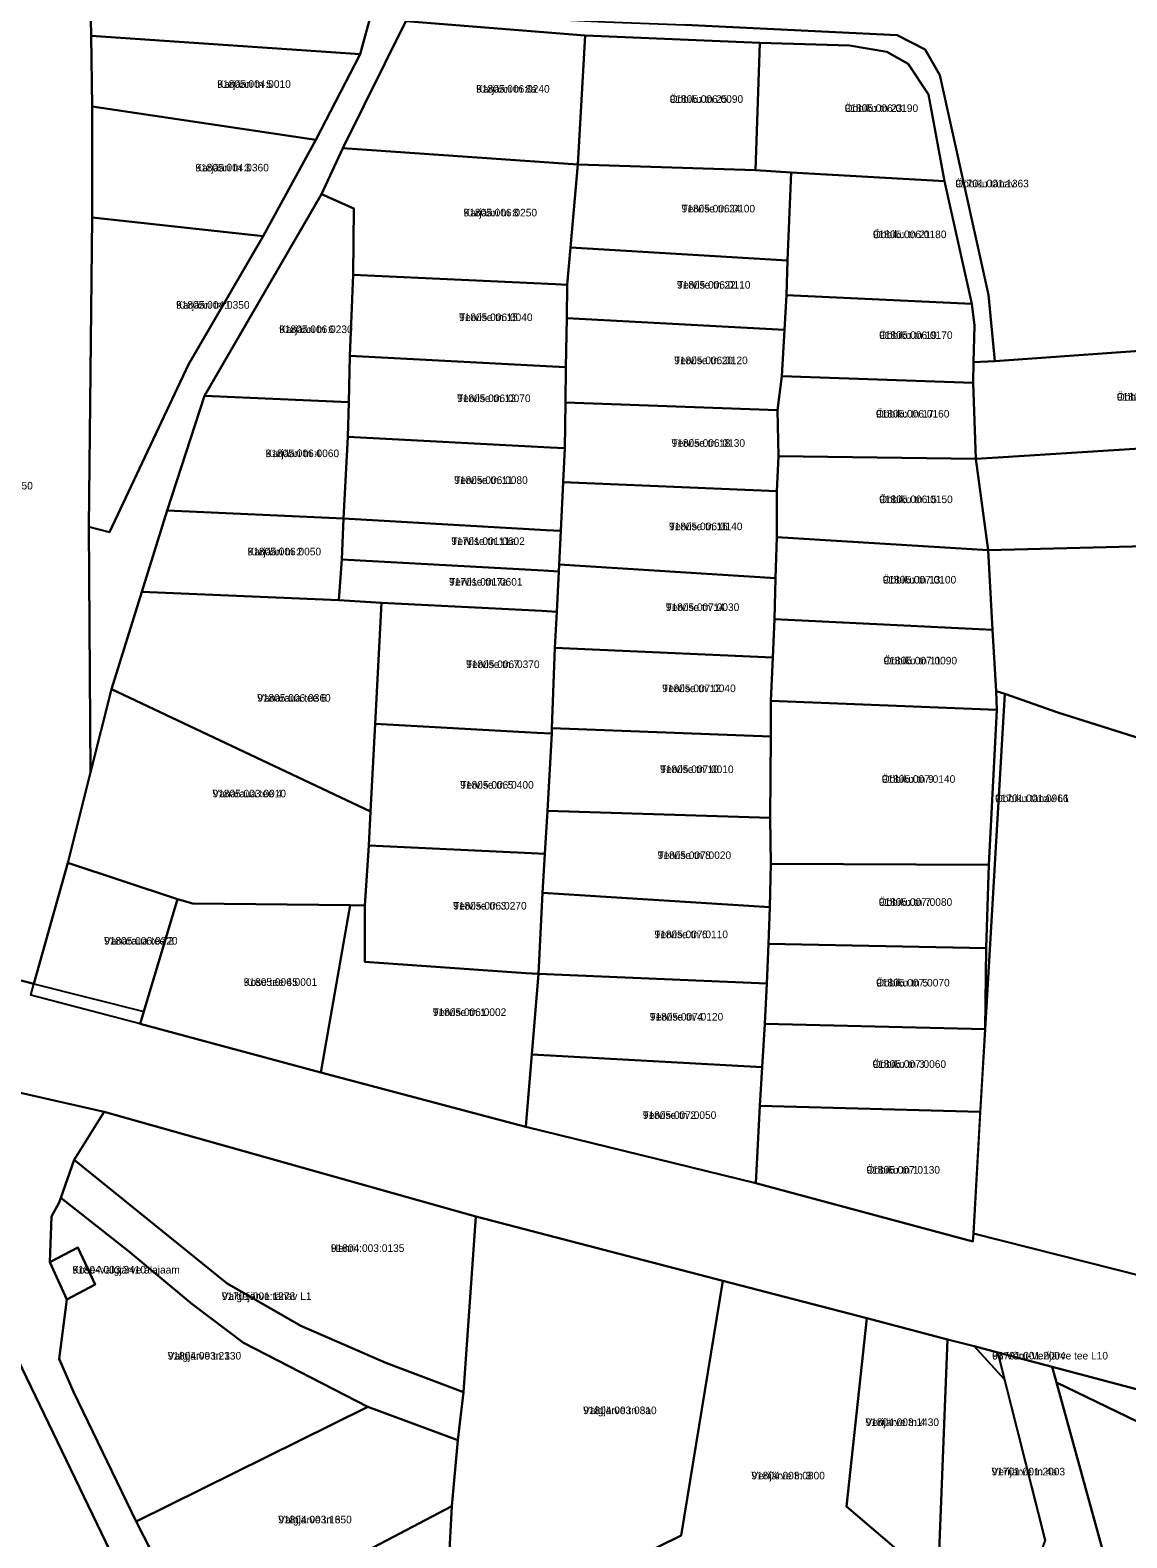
# Model space of a CAD drawing. Extents: x 655954 to 711923, y 6395079 to 6429745.
# Drawn here: x 680691.2 to 680907.6, y 6411990.7 to 6412288.3 of the extents above; entities that cross this region are included whole.
import ezdxf

# ---------------------------------------------------------------- set-up
doc = ezdxf.new("R2010")
doc.units = 0
for name, color, linetype in [('L_AADRESS', 7, 'Continuous'), ('PIIR', 7, 'Continuous'), ('TUNNUS', 7, 'Continuous')]:
    doc.layers.add(name, color=color, linetype=linetype)

msp = doc.modelspace()

# ---------------------------------------------------------------- linework, layer by layer
at = {"layer": 'PIIR'}
for points in [[(680680.44, 6412556.2), (680693.94, 6412462.74), (680699, 6412413.21), (680701.22, 6412382.72), (680702.09, 6412366.63), (680702.52, 6412349.92), (680702.33, 6412333.42), (680702.73, 6412319.59), (680702.93, 6412303.72), (680703.22, 6412287.2), (680703.43, 6412273.22), (680703.41, 6412251.32), (680702.8, 6412190.26), (680703.14, 6412141.77), (680698.64, 6412123.91), (680691.94, 6412100.04), (680672.88, 6412104.96)], [(680765.34, 6412290.1), (680752.9, 6412265.02), (680748.69, 6412255.94), (680725.61, 6412216.14), (680718.25, 6412193.46), (680713.24, 6412177.42), (680707.28, 6412158.21), (680703.14, 6412141.77), (680702.8, 6412190.26), (680706.83, 6412189.19), (680722.42, 6412222.3), (680737.18, 6412247.62), (680747.58, 6412266.64), (680756.31, 6412283.58), (680760.94, 6412300.49)], [(680933.18, 6412226.66), (680881.55, 6412222.94), (680880.28, 6412236.06), (680870.69, 6412279.41), (680867.78, 6412284.5), (680862.31, 6412287.31), (680820.36, 6412289.35)], [(680938.72, 6412035.25), (680877.31, 6412050.78), (680878.8, 6412076.38), (680879.65, 6412091.1), (680883.54, 6412157.28), (680894.01, 6412153.62), (680910.4, 6412148.38)], [(680672.88, 6412104.96), (680691.94, 6412100.04), (680713.61, 6412094.57), (680712.89, 6412092.18), (680748.53, 6412082.52), (680786.53, 6412072.49), (680788.99, 6412071.84), (680834.37, 6412060.69), (680877.19, 6412049.18), (680877.31, 6412050.78), (680938.72, 6412035.25), (680958.41, 6412030.09), (680992.85, 6412021.05), (680998.02, 6412019.7), (681048.15, 6412005.85), (681072.23, 6411999.62), (681095.85, 6411993.91), (681114.62, 6411989.2), (681131.81, 6411985.29), (681142.64, 6411981.4), (681196.38, 6411968), (681251.89, 6411953.79)], [(681715.24, 6411810.02), (681453.34, 6411877.71), (681294.84, 6411919.24), (681247.61, 6411931.95), (681196.28, 6411945.45), (681144.95, 6411958.58), (681138, 6411960.36), (681067.39, 6411978.82), (681030.99, 6411988.27), (680959.83, 6412006.81), (680933.06, 6412013.75), (680892.85, 6412024.44), (680882.14, 6412027.25), (680877.44, 6412028.49), (680872.22, 6412029.86), (680856.28, 6412034.04), (680827.85, 6412041.39), (680779.17, 6412054.12), (680705.81, 6412074.78), (680677.03, 6412081.28)], [(680677.03, 6412081.28), (680705.81, 6412074.78), (680699.91, 6412065.3), (680697.25, 6412057.81), (680696.92, 6412056.89), (680695.4, 6412054.12), (680695.07, 6412045.07), (680698.46, 6412037.72), (680696.92, 6412026.03), (680699.73, 6412019.48), (680712.13, 6411993.93), (680724.06, 6411970.51)], [(680713.98, 6411973.54), (680684.39, 6412034.88)], [(680891.46, 6411990.2), (680882.14, 6412027.25), (680892.85, 6412024.44), (680893.69, 6412021.37), (680905.86, 6411977.12)], [(680905.86, 6411977.12), (680893.69, 6412021.37), (680921.45, 6412007.92), (680932.14, 6412005.16), (680933.52, 6411996.33), (680936.54, 6411993.46), (680947.76, 6411994.27), (680949.96, 6411993.29), (680959.44, 6411986.97)]]:
    msp.add_lwpolyline(points, dxfattribs=at)
for points in [[(680760.94, 6412300.49), (680756.31, 6412283.58), (680703.22, 6412287.2), (680702.93, 6412303.72)], [(680752.9, 6412265.02), (680765.34, 6412290.1), (680800.73, 6412287.27), (680799.29, 6412261.81)], [(680870.69, 6412279.41), (680880.28, 6412236.06), (680881.55, 6412222.94), (680877.37, 6412222.76), (680877.54, 6412230), (680877.04, 6412234.3), (680871.65, 6412258.51), (680868.45, 6412275.6), (680864.46, 6412281.65), (680860.25, 6412284.01), (680852.84, 6412285.3), (680835.2, 6412285.8), (680800.73, 6412287.27), (680765.34, 6412290.1), (680767.12, 6412291.79), (680804.61, 6412289.94), (680820.36, 6412289.35), (680862.31, 6412287.31), (680867.78, 6412284.5)], [(680756.31, 6412283.58), (680747.58, 6412266.64), (680703.43, 6412273.22), (680703.22, 6412287.2)], [(680835.2, 6412285.8), (680834.35, 6412260.66), (680799.29, 6412261.81), (680800.73, 6412287.27)], [(680835.2, 6412285.8), (680852.84, 6412285.3), (680860.25, 6412284.01), (680864.46, 6412281.65), (680868.45, 6412275.6), (680871.65, 6412258.51), (680841.34, 6412260.19), (680834.35, 6412260.66)], [(680747.58, 6412266.64), (680737.18, 6412247.62), (680703.41, 6412251.32), (680703.43, 6412273.22)], [(680799.29, 6412261.81), (680797.82, 6412245.4), (680797.18, 6412238.06), (680794.89, 6412238.16), (680754.94, 6412239.99), (680755.08, 6412253.09), (680748.69, 6412255.94), (680752.9, 6412265.02)], [(680799.29, 6412261.81), (680834.35, 6412260.66), (680841.34, 6412260.19), (680840.67, 6412242.85), (680797.82, 6412245.4)], [(680840.46, 6412236.01), (680840.67, 6412242.85), (680841.34, 6412260.19), (680871.65, 6412258.51), (680877.04, 6412234.3)], [(680748.69, 6412255.94), (680755.08, 6412253.09), (680754.94, 6412239.99), (680754.31, 6412224.01), (680754.06, 6412214.85), (680725.61, 6412216.14)], [(680722.42, 6412222.3), (680706.83, 6412189.19), (680702.8, 6412190.26), (680703.41, 6412251.32), (680737.18, 6412247.62)], [(680797.08, 6412231.45), (680797.18, 6412238.06), (680797.82, 6412245.4), (680840.67, 6412242.85), (680840.46, 6412236.01), (680840.05, 6412229.16)], [(680754.31, 6412224.01), (680754.94, 6412239.99), (680794.89, 6412238.16), (680797.18, 6412238.06), (680797.08, 6412231.45), (680796.9, 6412221.77), (680794.26, 6412221.91)], [(680840.46, 6412236.01), (680877.04, 6412234.3), (680877.54, 6412230), (680877.37, 6412222.76), (680877.27, 6412218.69), (680839.53, 6412220), (680840.05, 6412229.16)], [(680840.05, 6412229.16), (680839.53, 6412220), (680838.65, 6412213.28), (680796.81, 6412214.83), (680796.9, 6412221.77), (680797.08, 6412231.45)], [(680882.15, 6412203.95), (680877.77, 6412203.66), (680877.27, 6412218.69), (680877.37, 6412222.76), (680881.55, 6412222.94), (680933.18, 6412226.66), (680934.3, 6412207.68), (680932.05, 6412207.12)], [(680753.87, 6412208.02), (680754.06, 6412214.85), (680754.31, 6412224.01), (680794.26, 6412221.91), (680796.9, 6412221.77), (680796.81, 6412214.83), (680796.69, 6412205.76), (680793.81, 6412205.92)], [(680877.27, 6412218.69), (680877.77, 6412203.66), (680838.87, 6412204.23), (680838.65, 6412213.28), (680839.53, 6412220)], [(680725.61, 6412216.14), (680754.06, 6412214.85), (680753.87, 6412208.02), (680753.03, 6412191.89), (680718.25, 6412193.46)], [(680838.65, 6412213.28), (680838.87, 6412204.23), (680838.51, 6412197.29), (680796.38, 6412199.08), (680796.69, 6412205.76), (680796.81, 6412214.83)], [(680753.03, 6412191.89), (680753.87, 6412208.02), (680793.81, 6412205.92), (680796.69, 6412205.76), (680796.38, 6412199.08), (680795.94, 6412189.44), (680793, 6412189.6)], [(680942.34, 6412187.24), (680880.22, 6412185.64), (680877.77, 6412203.66), (680882.15, 6412203.95), (680932.05, 6412207.12), (680934.3, 6412207.68), (680936.09, 6412202.44), (680940.09, 6412193.73)], [(680880.22, 6412185.64), (680838.56, 6412188.25), (680838.51, 6412197.29), (680838.87, 6412204.23), (680877.77, 6412203.66)], [(680838.51, 6412197.29), (680838.56, 6412188.25), (680838.3, 6412180.12), (680795.58, 6412182.85), (680795.94, 6412189.44), (680796.38, 6412199.08)], [(680718.25, 6412193.46), (680753.03, 6412191.89), (680752.7, 6412183.83), (680752.14, 6412175.81), (680713.24, 6412177.42)], [(680752.7, 6412183.83), (680753.03, 6412191.89), (680793, 6412189.6), (680795.94, 6412189.44), (680795.58, 6412182.85), (680795.52, 6412181.46), (680792.5, 6412181.65)], [(680880.22, 6412185.64), (680881.12, 6412169.9), (680838.1, 6412172.05), (680838.3, 6412180.12), (680838.56, 6412188.25)], [(680910.4, 6412148.38), (680894.01, 6412153.62), (680883.54, 6412157.28), (680881.81, 6412157.84), (680881.12, 6412169.9), (680880.22, 6412185.64), (680942.34, 6412187.24), (680942.89, 6412185.65), (680943.13, 6412183.74), (680943.17, 6412182.04), (680942.89, 6412180.73), (680941.35, 6412177.83), (680938.65, 6412173.58), (680934.19, 6412166.77), (680930.54, 6412161.41), (680927.17, 6412155.65), (680926.93, 6412154.82), (680926.32, 6412152.73), (680926.58, 6412150.84), (680912.52, 6412151.51), (680910.54, 6412151.62)], [(680752.14, 6412175.81), (680752.7, 6412183.83), (680792.5, 6412181.65), (680795.52, 6412181.46), (680795.12, 6412173.48), (680792.14, 6412173.66), (680760.52, 6412175.29)], [(680837.75, 6412164.44), (680794.76, 6412166.38), (680795.12, 6412173.48), (680795.52, 6412181.46), (680795.58, 6412182.85), (680838.3, 6412180.12), (680838.1, 6412172.05)], [(680707.28, 6412158.21), (680713.24, 6412177.42), (680752.14, 6412175.81), (680760.52, 6412175.29), (680759.27, 6412151.4), (680758.38, 6412134.06)], [(680759.27, 6412151.4), (680760.52, 6412175.29), (680792.14, 6412173.66), (680795.12, 6412173.48), (680794.76, 6412166.38), (680794.13, 6412150.49), (680794.14, 6412149.46), (680791.18, 6412149.62)], [(680881.93, 6412154.14), (680837.35, 6412155.92), (680837.75, 6412164.44), (680838.1, 6412172.05), (680881.12, 6412169.9), (680881.81, 6412157.84)], [(680794.76, 6412166.38), (680837.75, 6412164.44), (680837.35, 6412155.92), (680837.35, 6412148.88), (680794.13, 6412150.49)], [(680707.28, 6412158.21), (680758.38, 6412134.06), (680758, 6412127.38), (680757.22, 6412115.51), (680754.35, 6412115.56), (680723.27, 6412115.9), (680720.27, 6412116.78), (680698.64, 6412123.91), (680703.14, 6412141.77)], [(680837.35, 6412123.76), (680837.24, 6412132.84), (680837.35, 6412148.88), (680837.35, 6412155.92), (680881.93, 6412154.14), (680880.35, 6412123.54)], [(680880.35, 6412123.54), (680881.93, 6412154.14), (680881.81, 6412157.84), (680883.54, 6412157.28), (680879.65, 6412091.1), (680879.87, 6412107.11)], [(680758.38, 6412134.06), (680759.27, 6412151.4), (680791.18, 6412149.62), (680794.14, 6412149.46), (680793.26, 6412134.19), (680792.77, 6412125.74), (680790.11, 6412125.87), (680758, 6412127.38)], [(680794.13, 6412150.49), (680837.35, 6412148.88), (680837.24, 6412132.84), (680793.26, 6412134.19), (680794.14, 6412149.46)], [(680793.26, 6412134.19), (680837.24, 6412132.84), (680837.35, 6412123.76), (680837.16, 6412115.16), (680792.29, 6412118.01), (680792.77, 6412125.74)], [(680757.22, 6412115.51), (680758, 6412127.38), (680790.11, 6412125.87), (680792.77, 6412125.74), (680792.29, 6412118.01), (680791.48, 6412102.01), (680788.99, 6412102.18), (680757.22, 6412104.38)], [(680720.27, 6412116.78), (680713.61, 6412094.57), (680712.89, 6412092.18), (680691.31, 6412097.78), (680691.94, 6412100.04), (680698.64, 6412123.91)], [(680836.91, 6412107.93), (680837.16, 6412115.16), (680837.35, 6412123.76), (680880.35, 6412123.54), (680879.87, 6412107.11)], [(680713.61, 6412094.57), (680720.27, 6412116.78), (680723.27, 6412115.9), (680754.35, 6412115.56), (680748.53, 6412082.52), (680712.89, 6412092.18)], [(680792.29, 6412118.01), (680837.16, 6412115.16), (680836.91, 6412107.93), (680836.55, 6412100.1), (680791.48, 6412102.01)], [(680754.35, 6412115.56), (680757.22, 6412115.51), (680757.22, 6412104.38), (680788.99, 6412102.18), (680791.48, 6412102.01), (680790.17, 6412086.07), (680789.2, 6412074.33), (680788.99, 6412071.84), (680786.53, 6412072.49), (680748.53, 6412082.52)], [(680836.17, 6412092.15), (680836.55, 6412100.1), (680836.91, 6412107.93), (680879.87, 6412107.11), (680879.65, 6412091.1)], [(680791.48, 6412102.01), (680836.55, 6412100.1), (680836.17, 6412092.15), (680835.67, 6412083.58), (680790.17, 6412086.07)], [(680835.21, 6412075.96), (680835.67, 6412083.58), (680836.17, 6412092.15), (680879.65, 6412091.1), (680878.68, 6412074.78)], [(680788.99, 6412071.84), (680789.2, 6412074.33), (680790.17, 6412086.07), (680835.67, 6412083.58), (680835.21, 6412075.96), (680834.37, 6412060.69)], [(680834.37, 6412060.69), (680835.21, 6412075.96), (680878.68, 6412074.78), (680877.31, 6412050.78), (680877.19, 6412049.18)], [(680705.81, 6412074.78), (680779.17, 6412054.12), (680776.74, 6412019.45), (680761.41, 6412025.2), (680744.61, 6412032.55), (680730.06, 6412040.92), (680699.91, 6412065.3)], [(680776.74, 6412019.45), (680775.57, 6412009.98), (680757.85, 6412016.57), (680733.3, 6412029.15), (680723.13, 6412036.9), (680710.53, 6412047.33), (680697.25, 6412057.81), (680699.91, 6412065.3), (680730.06, 6412040.92), (680744.61, 6412032.55), (680761.41, 6412025.2)], [(680712.13, 6411993.93), (680699.73, 6412019.48), (680696.92, 6412026.03), (680698.46, 6412037.72), (680704, 6412040.68), (680700.63, 6412048), (680695.07, 6412045.07), (680695.4, 6412054.12), (680696.92, 6412056.89), (680697.25, 6412057.81), (680710.53, 6412047.33), (680723.13, 6412036.9), (680733.3, 6412029.15), (680757.85, 6412016.57), (680750.78, 6412013.05)], [(680779.17, 6412054.12), (680827.85, 6412041.39), (680819.65, 6411991.16), (680798.16, 6411980.54), (680772.8, 6411967.11), (680772.87, 6411968.3), (680774.4, 6411996.9), (680775.57, 6412009.98), (680776.74, 6412019.45)], [(680695.07, 6412045.07), (680700.63, 6412048), (680704, 6412040.68), (680698.46, 6412037.72)], [(680827.85, 6412041.39), (680856.28, 6412034.04), (680852.3, 6411996.87), (680868.87, 6411982.71), (680812.55, 6411953.72), (680798.16, 6411980.54), (680819.65, 6411991.16)], [(680676.96, 6412036.82), (680684.39, 6412034.88), (680713.98, 6411973.54), (680635.38, 6411927.25), (680633.49, 6411926.26), (680628.89, 6411931.55), (680620.27, 6411940.29), (680614.08, 6411945.87), (680608.86, 6411949.03), (680604.98, 6411952.79), (680600.49, 6411956.92), (680594.02, 6411961.84), (680595.49, 6411963.69), (680604.05, 6411974.9), (680611.8, 6412018.81), (680620.2, 6412023.18), (680625.29, 6412012.56)], [(680866.23, 6411976.51), (680868.87, 6411982.71), (680852.3, 6411996.87), (680856.28, 6412034.04), (680872.22, 6412029.86), (680870.35, 6411982.89), (680870.07, 6411975.87), (680895.55, 6411967.56), (680891.03, 6411954.2), (680882.6, 6411950.1), (680829.67, 6411924.45), (680816.54, 6411950.53)], [(680889.38, 6411984.65), (680885.22, 6411980.63), (680870.35, 6411982.89), (680872.22, 6412029.86), (680877.44, 6412028.49), (680883.48, 6412021.94), (680891.46, 6411990.2)], [(680882.14, 6412027.25), (680883.48, 6412021.94), (680877.44, 6412028.49)], [(680892.85, 6412024.44), (680933.06, 6412013.75), (680931.64, 6412008.37), (680932.14, 6412005.16), (680921.45, 6412007.92), (680893.69, 6412021.37)], [(680712.13, 6411993.93), (680750.78, 6412013.05), (680757.85, 6412016.57), (680775.57, 6412009.98), (680774.4, 6411996.9), (680724.06, 6411970.51)], [(680772.8, 6411967.11), (680735.54, 6411948.29), (680724.06, 6411970.51), (680774.4, 6411996.9)]]:
    msp.add_lwpolyline(points, close=True, dxfattribs=at)

# ---------------------------------------------------------------- texts
at = {"layer": 'L_AADRESS'}
for s, p in [('Karjääri tn 5', (680728.13, 6412276.92)), ('Karjääri tn 8a', (680779.21, 6412275.96)), ('Ööbiku tn 25', (680817.39, 6412273.96)), ('Ööbiku tn 23', (680851.92, 6412272.16)), ('Karjääri tn 3', (680723.8, 6412260.42)), ('Ööbiku tänav', (680873.76, 6412257.28)), ('Tervise tn 24', (680819.74, 6412252.33)), ('Karjääri tn 8', (680776.72, 6412251.54)), ('Ööbiku tn 21', (680857.5, 6412247.25)), ('Tervise tn 22', (680818.83, 6412237.28)), ('Karjääri tn 1', (680719.99, 6412233.32)), ('Karjääri tn 6', (680740.34, 6412228.51)), ('Tervise tn 15', (680775.83, 6412230.88)), ('Ööbiku tn 19', (680858.71, 6412227.35)), ('Tervise tn 20', (680818.29, 6412222.37)), ('Tervise tn 13', (680775.44, 6412214.89)), ('Ööbiku tn 6', (680905.62, 6412215.16)), ('Ööbiku tn 17', (680858.09, 6412211.83)), ('Tervise tn 18', (680817.76, 6412206.06)), ('Karjääri tn 4', (680737.67, 6412204.02)), ('Tervise tn 11', (680774.88, 6412198.73)), ('Ööbiku tn 15', (680858.74, 6412194.94)), ('Tervise tn 16', (680817.25, 6412189.6)), ('Tervise tn 11a', (680774.3, 6412186.68)), ('Karjääri tn 2', (680734.11, 6412184.63)), ('Tervise tn 7a', (680773.86, 6412178.65)), ('Ööbiku tn 13', (680859.43, 6412179.07)), ('Tervise tn 14', (680816.63, 6412173.65)), ('Ööbiku tn 11', (680859.6, 6412163.1)), ('Tervise tn 7', (680777.22, 6412162.38)), ('Tervise tn 12', (680815.92, 6412157.63)), ('Vanaraua tee 6', (680736, 6412155.74)), ('Tervise tn 10', (680815.5, 6412141.66)), ('Ööbiku tn 9', (680859.24, 6412139.73)), ('Vanaraua tee 4', (680727.18, 6412136.86)), ('Tervise tn 5', (680776.06, 6412138.57)), ('Ööbiku tänav L1', (680881.59, 6412135.92)), ('Tervise tn 8', (680815.02, 6412124.68)), ('Ööbiku tn 7', (680858.64, 6412115.44)), ('Tervise tn 3', (680774.67, 6412114.7)), ('Tervise tn 6', (680814.39, 6412109.06)), ('Vanaraua tee 2', (680705.79, 6412107.79)), ('Kose tee 45', (680733.34, 6412099.65)), ('Ööbiku tn 5', (680858.14, 6412099.52)), ('Tervise tn 1', (680770.65, 6412093.7)), ('Tervise tn 4', (680813.46, 6412092.79)), ('Ööbiku tn 3', (680857.43, 6412083.46)), ('Tervise tn 2', (680812.09, 6412073.38)), ('Ööbiku tn 1', (680856.23, 6412062.57)), ('Henri', (680750.54, 6412047.12)), ('Kose-Valgjärve alajaam', (680699.54, 6412042.86)), ('Valgejärve tänav L1', (680729, 6412037.64)), ('Valgjärve tn 1', (680718.34, 6412025.87)), ('66 Võru-Verijärve tee L10', (680881.02, 6412025.89)), ('Valgjärve tn 3a', (680800.32, 6412015.1)), ('Verijärve tn 4', (680856.04, 6412012.76)), ('Verijärve tn 3', (680833.51, 6412002.22)), ('Verijärve tn 4a', (680880.91, 6412003.01)), ('Valgjärve tn 3', (680740.16, 6411993.54))]:
    msp.add_text(s, height=1.5, dxfattribs=at).set_placement(p)
at = {"layer": 'TUNNUS'}
for s, p in [('91805:004:0010', (680728.13, 6412276.92)), ('91805:006:0240', (680779.21, 6412275.96)), ('91805:006:0090', (680817.39, 6412273.96)), ('91805:006:0190', (680851.92, 6412272.16)), ('91805:004:0360', (680723.8, 6412260.42)), ('91701:001:1363', (680873.76, 6412257.28)), ('91805:006:0100', (680819.74, 6412252.33)), ('91805:006:0250', (680776.72, 6412251.54)), ('91805:006:0180', (680857.5, 6412247.25)), ('91805:006:0110', (680818.83, 6412237.28)), ('91805:004:0350', (680719.99, 6412233.32)), ('91805:006:0230', (680740.34, 6412228.51)), ('91805:006:0040', (680775.83, 6412230.88)), ('91805:006:0170', (680858.71, 6412227.35)), ('91805:006:0120', (680818.29, 6412222.37)), ('91805:006:0070', (680775.44, 6412214.89)), ('91805:006:0300', (680905.62, 6412215.16)), ('91805:006:0160', (680858.09, 6412211.83)), ('91805:006:0130', (680817.76, 6412206.06)), ('91805:006:0060', (680737.67, 6412204.02)), ('91805:006:0080', (680774.88, 6412198.73)), ('91805:004:0150', (680677.23, 6412197.64)), ('91805:006:0150', (680858.74, 6412194.94)), ('91805:006:0140', (680817.25, 6412189.6)), ('91701:001:0602', (680774.3, 6412186.68)), ('91805:006:0050', (680734.11, 6412184.63)), ('91701:001:0601', (680773.86, 6412178.65)), ('91805:007:0100', (680859.43, 6412179.07)), ('91805:007:0030', (680816.63, 6412173.65)), ('91805:007:0090', (680859.6, 6412163.1)), ('91805:006:0370', (680777.22, 6412162.38)), ('91805:007:0040', (680815.92, 6412157.63)), ('91805:006:0360', (680736, 6412155.74)), ('91805:007:0010', (680815.5, 6412141.66)), ('91805:007:0140', (680859.24, 6412139.73)), ('91805:003:0010', (680727.18, 6412136.86)), ('91805:006:0400', (680776.06, 6412138.57)), ('91701:001:0966', (680881.59, 6412135.92)), ('91805:007:0020', (680815.02, 6412124.68)), ('91805:007:0080', (680858.64, 6412115.44)), ('91805:006:0270', (680774.67, 6412114.7)), ('91805:007:0110', (680814.39, 6412109.06)), ('91805:006:0220', (680705.79, 6412107.79)), ('91805:006:0001', (680733.34, 6412099.65)), ('91805:007:0070', (680858.14, 6412099.52)), ('91805:006:0002', (680770.65, 6412093.7)), ('91805:007:0120', (680813.46, 6412092.79)), ('91805:007:0060', (680857.43, 6412083.46)), ('91805:007:0050', (680812.09, 6412073.38)), ('91805:007:0130', (680856.23, 6412062.57)), ('91804:003:0135', (680750.54, 6412047.12)), ('91804:003:3410', (680699.54, 6412042.86)), ('91701:001:1278', (680729, 6412037.64)), ('91804:003:2330', (680718.34, 6412025.87)), ('91701:001:2004', (680881.02, 6412025.89)), ('91804:003:0810', (680800.32, 6412015.1)), ('91804:003:1430', (680856.04, 6412012.76)), ('91804:003:0800', (680833.51, 6412002.22)), ('91701:001:2003', (680880.91, 6412003.01)), ('91804:003:1650', (680740.16, 6411993.54))]:
    msp.add_text(s, height=1.5, dxfattribs=at).set_placement(p)

doc.saveas('drawing.dxf')
